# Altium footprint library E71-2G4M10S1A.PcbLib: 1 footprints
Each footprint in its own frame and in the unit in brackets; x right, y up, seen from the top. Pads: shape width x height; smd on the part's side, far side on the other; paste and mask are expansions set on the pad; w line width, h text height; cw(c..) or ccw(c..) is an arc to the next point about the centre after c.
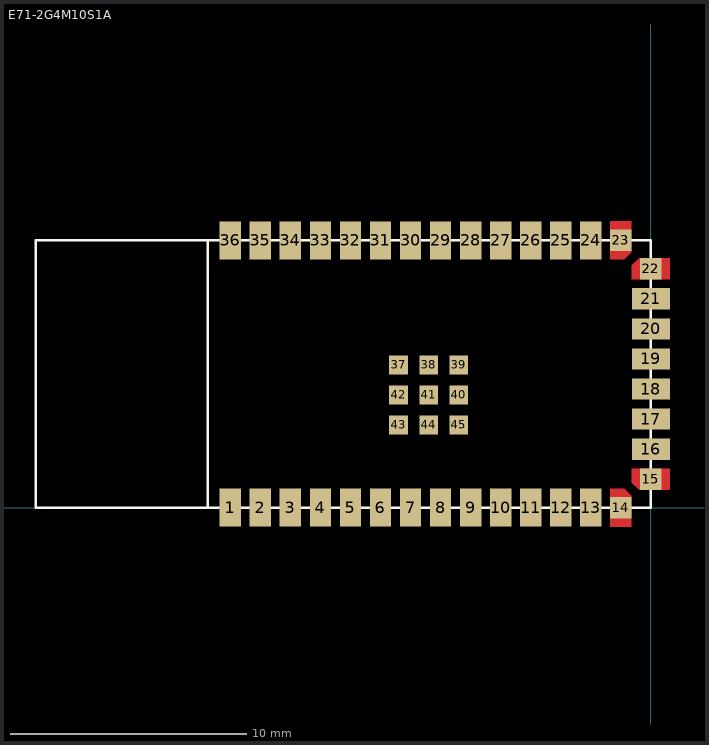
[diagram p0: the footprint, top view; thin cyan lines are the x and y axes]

## E71-2G4M10S1A [mm]
pads (48):
  rect 0.9x1.6 smd: 1(-17.78,0) 2(-16.51,0) 3(-15.24,0) 4(-13.97,0) 5(-12.7,0) 6(-11.43,0) 7(-10.16,0) 8(-8.89,0) 9(-7.62,0) 10(-6.35,0) 11(-5.08,0) 12(-3.81,0) 13(-2.54,0) 24(-2.54,11.3) 25(-3.81,11.3) 26(-5.08,11.3) 27(-6.35,11.3) 28(-7.62,11.3) 29(-8.89,11.3) 30(-10.16,11.3) 31(-11.43,11.3) 32(-12.7,11.3) 33(-13.97,11.3) 34(-15.24,11.3) 35(-16.51,11.3) 36(-17.78,11.3)
  rect 0.9x0.9 smd: 14(-1.27,0) 15(0,1.205) 15(0,1.205) 22(0,10.095) 22(0,10.095) 23(-1.27,11.3) 23(-1.27,11.3)
  rect 1.6x0.9 smd: 16(0,2.475) 17(0,3.745) 18(0,5.015) 19(0,6.285) 20(0,7.555) 21(0,8.825)
  rect 0.8x0.8 smd: 37(-10.662,6.039) 38(-9.392,6.039) 39(-8.122,6.039) 40(-8.122,4.769) 41(-9.392,4.769) 42(-10.662,4.769) 43(-10.662,3.499) 44(-9.392,3.499) 45(-8.122,3.499)
Top Layer:
  region: -1.72,10.5 -1.12,10.5 -0.82,10.8 -0.82,12.1 -1.72,12.1
  region: -0.8,9.645 -0.8,10.245 -0.5,10.545 0.8,10.545 0.8,9.645
  region: -0.8,1.655 -0.8,1.055 -0.5,0.755 0.8,0.755 0.8,1.655
  region: -1.72,0.8 -1.12,0.8 -0.82,0.5 -0.82,-0.8 -1.72,-0.8
Top Overlay:
  lines w0.1: -18.725,0 -18.725,11.3 ; -26,0 -26,11.3 0,11.3 0,0 -26,0
Top Paste:
  region: -1.72,10.5 -1.12,10.5 -0.82,10.8 -0.82,12.1 -1.72,12.1
  region: -0.8,9.645 -0.8,10.245 -0.5,10.545 0.8,10.545 0.8,9.645
  region: -0.8,1.655 -0.8,1.055 -0.5,0.755 0.8,0.755 0.8,1.655
  region: -1.72,0.8 -1.12,0.8 -0.82,0.5 -0.82,-0.8 -1.72,-0.8
Top Solder:
  region: -1.82,10.4 -1.12,10.4 -0.72,10.8 -0.72,12.2 -1.82,12.2
  region: -0.9,9.545 -0.9,10.245 -0.5,10.645 0.9,10.645 0.9,9.545
  region: -0.9,1.755 -0.9,1.055 -0.5,0.655 0.9,0.655 0.9,1.755
  region: -1.82,0.9 -1.12,0.9 -0.72,0.5 -0.72,-0.9 -1.82,-0.9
